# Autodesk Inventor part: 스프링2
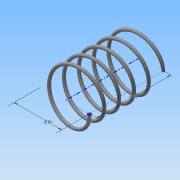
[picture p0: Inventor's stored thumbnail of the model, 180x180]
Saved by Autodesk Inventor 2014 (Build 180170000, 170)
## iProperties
Created: 2015-06
Part Number: 스프링2
Material: 강철, 연강
Document SubType Name: Modeling
Designer: MYHOME
Density: 1 g/cm^3
Appearance: 강철
Author: MYHOME
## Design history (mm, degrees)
sketch "스케치1"
  geometry: L1 (0, 0)-(8, 0); L2 (8, 0)-(8, 14.5); L3 (8, 14.5)-(0, 14.5); L4 (0, 14.5)-(0, 0); C1 r 0.5 at (8, 0)
  constraints: 8 end point, 2 parallel, 1 centre point, 1 coincident, 1 horizontal, 1 perpendicular
  dimensions: "d0" = 16 diameter of L2 L4; "d1" = 14.5 distance of L1.end L2.end (derived); "d2" = 1 diameter of C1
feature "코일2" sketch "스케치1" pitch "d17" = 10; turns "d19" = 5; dims "d18" = 14.5 (= d1), "d20" = 0, angle "d21" = 90 deg, angle "d22" = 90 deg, "d23" = 0, "d24" = 0
node "작업 평면3"
sketch "스케치4"
  geometry: L1 (-8.5, 0)-(-7.5, 0) reference; 1 further point
  constraints: 1 horizontal alignment
extrude "돌출3" cut sketch "스케치4" stored distance "d26" = 10; taper "d27" = 0 deg
node "작업 평면4"
sketch "스케치5"
  geometry: L1 (-7.5, 0)-(-8.5, 0) reference; 1 further point
  constraints: 1 horizontal alignment
extrude "돌출4" cut sketch "스케치5" stored distance "d29" = 10; taper "d30" = 0 deg
node "솔리드2"
node "절단 모서리 투영3"
node "절단 모서리 투영4"
other parameters: "d25" = 0, "d28" = 14.5 (= d1)
